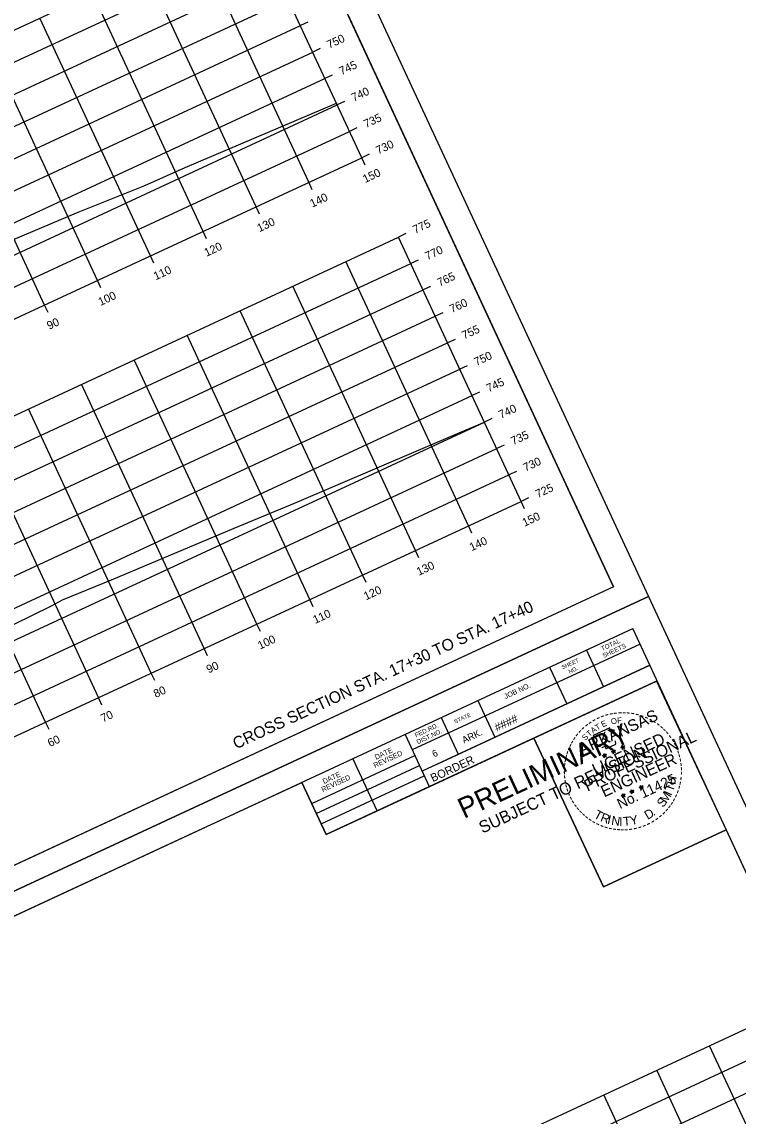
# Model space of a CAD drawing. Extents: x 1354696 to 1366163, y 660729 to 670380.
# Drawn here: x 1358197.6 to 1358320.5, y 665980.8 to 666168.5 of the extents above; entities that cross this region are included whole.
import ezdxf

# ---------------------------------------------------------------- set-up
doc = ezdxf.new("R2010")
doc.units = 0
for name, color, linetype in [('R_Axis', 7, 'Continuous'), ('R_Axis Annot', 7, 'Continuous'), ('R_Border', 7, 'Continuous'), ('R_Border PE', 7, 'Continuous'), ('R_Border Prem', 7, 'Continuous'), ('R_Draft', 7, 'Continuous'), ('R_Exist Surface', 7, 'Continuous'), ('R_Grid', 7, 'Continuous'), ('R_No Plot', 7, 'Continuous')]:
    doc.layers.add(name, color=color, linetype=linetype)

msp = doc.modelspace()

# ---------------------------------------------------------------- linework, layer by layer
at = {"layer": 'R_Axis'}
for p, q in [((1358255.9, 666145.21), (1358236.95, 666186.02)), ((1358246.64, 666168.47), (1358245.37, 666167.88)), ((1358248.75, 666163.94), (1358247.48, 666163.35)), ((1358250.85, 666159.4), (1358249.58, 666158.81)), ((1358252.96, 666154.87), (1358251.69, 666154.28)), ((1358255.06, 666150.33), (1358253.79, 666149.74)), ((1357983.8, 666018.88), (1358255.9, 666145.21)), ((1358257.17, 666145.8), (1358255.9, 666145.21)), ((1358256.49, 666143.94), (1358255.9, 666145.21)), ((1358247.42, 666139.73), (1358246.83, 666141)), ((1358238.35, 666135.52), (1358237.76, 666136.79)), ((1358229.28, 666131.31), (1358228.69, 666132.58)), ((1358263.49, 666132.19), (1358262.22, 666131.6)), ((1358283.27, 666086.25), (1358262.22, 666131.6)), ((1358220.21, 666127.1), (1358219.62, 666128.37)), ((1358265.59, 666127.66), (1358264.32, 666127.07)), ((1358211.14, 666122.88), (1358210.55, 666124.15)), ((1358267.7, 666123.12), (1358266.43, 666122.53)), ((1358202.07, 666118.67), (1358201.48, 666119.94)), ((1358269.8, 666118.59), (1358268.53, 666118)), ((1358271.91, 666114.05), (1358270.64, 666113.46)), ((1358274.01, 666109.52), (1358272.74, 666108.93)), ((1358276.12, 666104.98), (1358274.85, 666104.39)), ((1358278.22, 666100.45), (1358276.95, 666099.86)), ((1358280.33, 666095.91), (1358279.06, 666095.32)), ((1358282.44, 666091.38), (1358281.17, 666090.79)), ((1358011.17, 665959.92), (1358283.27, 666086.25)), ((1358284.54, 666086.84), (1358283.27, 666086.25)), ((1358283.86, 666084.98), (1358283.27, 666086.25)), ((1358274.79, 666080.77), (1358274.2, 666082.04)), ((1358265.72, 666076.56), (1358265.13, 666077.83)), ((1358256.65, 666072.35), (1358256.06, 666073.62)), ((1358247.58, 666068.14), (1358246.99, 666069.41)), ((1358238.51, 666063.93), (1358237.92, 666065.2)), ((1358229.44, 666059.72), (1358228.85, 666060.99)), ((1358220.37, 666055.51), (1358219.78, 666056.78)), ((1358211.3, 666051.3), (1358210.71, 666052.57)), ((1358202.23, 666047.08), (1358201.64, 666048.35))]:
    msp.add_line(p, q, dxfattribs=at)
at = {"layer": 'R_Border'}
for p, q in [((1358299.11, 666071.56), (1358212.59, 666257.91)), ((1358299.11, 666071.56), (1358012.33, 665938.41)), ((1358015.65, 665931.27), (1358302.43, 666064.41)), ((1358388.95, 665878.06), (1358302.43, 666064.41)), ((1358303.67, 666061.75), (1358264.58, 666043.6)), ((1358303.66, 666061.76), (1358303.66, 666061.76)), ((1358294.45, 666060.71), (1358297.37, 666054.41)), ((1358305.35, 666058.12), (1358266.26, 666039.97)), ((1358268.94, 666041.21), (1358305.35, 666058.12)), ((1358288.15, 666057.78), (1358291.08, 666051.49)), ((1358306.59, 666055.45), (1358249.77, 666029.07)), ((1358275.84, 666052.07), (1358278.76, 666045.77)), ((1358269.54, 666049.14), (1358272.46, 666042.85)), ((1358263.34, 666046.26), (1358267.5, 666037.3)), ((1358247.31, 666034.39), (1358265.03, 666042.62)), ((1358258.55, 666033.15), (1358254.39, 666042.11)), ((1358248.09, 666032.7), (1358265.81, 666040.93)), ((1358248.91, 666030.94), (1358266.63, 666039.17)), ((1358249.77, 666029.07), (1358245.61, 666038.03))]:
    msp.add_line(p, q, dxfattribs=at)
at = {"layer": 'R_Border PE'}
for p, q in [((1358297.59, 666042.61), (1358297.44, 666042.94)), ((1358297.44, 666042.94), (1358297.59, 666042.74)), ((1358297.44, 666042.94), (1358297.51, 666042.7)), ((1358297.86, 666042.86), (1358297.59, 666042.61)), ((1358297.86, 666042.86), (1358297.62, 666042.69)), ((1358297.86, 666042.86), (1358297.72, 666042.68)), ((1358298.74, 666043.27), (1358298.99, 666043.34)), ((1358298.74, 666043.27), (1358299.11, 666043.32)), ((1358298.74, 666043.27), (1358299.01, 666043.26)), ((1358299.11, 666043.32), (1358298.95, 666043.65)), ((1358298.95, 666043.65), (1358299.1, 666043.44)), ((1358298.95, 666043.65), (1358299.02, 666043.4)), ((1358299.04, 666042.96), (1358299.11, 666043.32)), ((1358299.04, 666042.96), (1358299.14, 666043.24)), ((1358299.04, 666042.96), (1358299.05, 666043.23)), ((1358299.38, 666043.56), (1358299.11, 666043.32)), ((1358299.43, 666043.14), (1358299.11, 666043.32)), ((1358299.38, 666043.56), (1358299.14, 666043.4)), ((1358299.43, 666043.14), (1358299.14, 666043.24)), ((1358299.43, 666043.14), (1358299.18, 666043.34)), ((1358299.38, 666043.56), (1358299.23, 666043.38)), ((1358300.35, 666044), (1358300.6, 666044.07)), ((1358300.35, 666044), (1358300.71, 666044.05)), ((1358300.35, 666044), (1358300.62, 666043.99)), ((1358300.71, 666044.05), (1358300.56, 666044.38)), ((1358300.56, 666044.38), (1358300.71, 666044.17)), ((1358300.56, 666044.38), (1358300.63, 666044.13)), ((1358300.64, 666043.69), (1358300.71, 666044.05)), ((1358300.64, 666043.69), (1358300.75, 666043.97)), ((1358300.64, 666043.69), (1358300.65, 666043.96)), ((1358300.98, 666044.29), (1358300.71, 666044.05)), ((1358301.03, 666043.87), (1358300.71, 666044.05)), ((1358300.98, 666044.29), (1358300.74, 666044.13)), ((1358301.03, 666043.87), (1358300.75, 666043.97)), ((1358301.03, 666043.87), (1358300.78, 666044.07)), ((1358300.98, 666044.29), (1358300.84, 666044.12)), ((1358297.23, 666042.57), (1358297.48, 666042.63)), ((1358297.23, 666042.57), (1358297.59, 666042.61)), ((1358297.23, 666042.57), (1358297.5, 666042.56)), ((1358297.52, 666042.25), (1358297.59, 666042.61)), ((1358297.52, 666042.25), (1358297.63, 666042.54)), ((1358297.52, 666042.25), (1358297.53, 666042.53)), ((1358297.91, 666042.43), (1358297.59, 666042.61)), ((1358297.91, 666042.43), (1358297.63, 666042.54)), ((1358297.91, 666042.43), (1358297.66, 666042.64)), ((1358303.9, 666037.18), (1358303.75, 666037.51)), ((1358303.75, 666037.51), (1358303.9, 666037.31)), ((1358303.75, 666037.51), (1358303.81, 666037.27)), ((1358304.17, 666037.43), (1358303.9, 666037.18)), ((1358304.17, 666037.43), (1358303.93, 666037.26)), ((1358304.22, 666037), (1358303.97, 666037.21)), ((1358304.17, 666037.43), (1358304.03, 666037.25)), ((1358300.42, 666035.7), (1358300.66, 666035.76)), ((1358300.42, 666035.7), (1358300.78, 666035.74)), ((1358300.42, 666035.7), (1358300.68, 666035.69)), ((1358300.78, 666035.74), (1358300.63, 666036.07)), ((1358300.63, 666036.07), (1358300.77, 666035.87)), ((1358300.63, 666036.07), (1358300.69, 666035.83)), ((1358300.71, 666035.38), (1358300.78, 666035.74)), ((1358300.71, 666035.38), (1358300.81, 666035.67)), ((1358300.71, 666035.38), (1358300.72, 666035.66)), ((1358301.05, 666035.99), (1358300.78, 666035.74)), ((1358301.1, 666035.56), (1358300.78, 666035.74)), ((1358301.05, 666035.99), (1358300.81, 666035.82)), ((1358301.1, 666035.56), (1358300.81, 666035.67)), ((1358301.1, 666035.56), (1358300.85, 666035.77)), ((1358301.05, 666035.99), (1358300.9, 666035.81)), ((1358301.93, 666036.4), (1358302.18, 666036.46)), ((1358301.93, 666036.4), (1358302.29, 666036.45)), ((1358301.93, 666036.4), (1358302.2, 666036.39)), ((1358302.29, 666036.45), (1358302.14, 666036.78)), ((1358302.14, 666036.78), (1358302.29, 666036.57)), ((1358302.14, 666036.78), (1358302.21, 666036.53)), ((1358302.22, 666036.08), (1358302.29, 666036.45)), ((1358302.22, 666036.08), (1358302.32, 666036.37)), ((1358302.22, 666036.08), (1358302.23, 666036.36)), ((1358302.56, 666036.69), (1358302.29, 666036.45)), ((1358302.61, 666036.27), (1358302.29, 666036.45)), ((1358302.56, 666036.69), (1358302.32, 666036.53)), ((1358302.61, 666036.27), (1358302.33, 666036.37)), ((1358302.61, 666036.27), (1358302.36, 666036.47)), ((1358302.56, 666036.69), (1358302.42, 666036.51)), ((1358303.54, 666037.13), (1358303.78, 666037.2)), ((1358303.54, 666037.13), (1358303.9, 666037.18)), ((1358303.54, 666037.13), (1358303.8, 666037.12)), ((1358303.83, 666036.82), (1358303.9, 666037.18)), ((1358303.83, 666036.82), (1358303.93, 666037.11)), ((1358303.83, 666036.82), (1358303.84, 666037.09)), ((1358304.22, 666037), (1358303.9, 666037.18)), ((1358304.22, 666037), (1358303.93, 666037.1))]:
    msp.add_line(p, q, dxfattribs=at)
for points in [[(1358299.21, 666046.74), (1358299.22, 666047.06), (1358298.61, 666046.75), (1358298.46, 666047.41), (1358295.63, 666046.1)], [(1358295.63, 666046.1), (1358296.23, 666045.46)], [(1358297.1, 666044.11), (1358297.14, 666044.03), (1358297.66, 666044.25), (1358297.81, 666043.8), (1358299.5, 666044.59), (1358299.46, 666045.16)], [(1358297.44, 666042.94), (1358297.91, 666042.43), (1358297.23, 666042.57), (1358297.86, 666042.86), (1358297.52, 666042.25), (1358297.44, 666042.94)], [(1358298.95, 666043.65), (1358299.43, 666043.14), (1358298.74, 666043.27), (1358299.38, 666043.56), (1358299.04, 666042.96), (1358298.95, 666043.65)], [(1358300.56, 666044.38), (1358301.03, 666043.87), (1358300.35, 666044), (1358300.98, 666044.29), (1358300.64, 666043.69), (1358300.56, 666044.38)], [(1358303.75, 666037.51), (1358304.22, 666037), (1358303.54, 666037.13), (1358304.17, 666037.43), (1358303.83, 666036.82), (1358303.75, 666037.51)], [(1358300.63, 666036.07), (1358301.1, 666035.56), (1358300.42, 666035.7), (1358301.05, 666035.99), (1358300.71, 666035.38), (1358300.63, 666036.07)], [(1358302.14, 666036.78), (1358302.61, 666036.27), (1358301.93, 666036.4), (1358302.56, 666036.69), (1358302.22, 666036.08), (1358302.14, 666036.78)]]:
    msp.add_lwpolyline(points, dxfattribs=at)
for centre, radius in [((1358299.11, 666043.32), 0.172), ((1358299.11, 666043.32), 0.145), ((1358299.11, 666043.32), 0.116), ((1358299.11, 666043.32), 0.0991), ((1358299.11, 666043.32), 0.0747), ((1358299.11, 666043.32), 0.0495), ((1358299.11, 666043.32), 0.0296), ((1358300.71, 666044.05), 0.172), ((1358300.71, 666044.05), 0.145), ((1358300.71, 666044.05), 0.116), ((1358300.71, 666044.05), 0.0991), ((1358300.71, 666044.05), 0.0747), ((1358300.71, 666044.05), 0.0495), ((1358300.71, 666044.05), 0.0296), ((1358297.59, 666042.61), 0.172), ((1358297.59, 666042.61), 0.145), ((1358297.59, 666042.61), 0.116), ((1358297.59, 666042.61), 0.0991), ((1358297.59, 666042.61), 0.0747), ((1358297.59, 666042.61), 0.0495), ((1358297.59, 666042.61), 0.0296), ((1358303.9, 666037.18), 0.172), ((1358303.9, 666037.18), 0.145), ((1358303.9, 666037.18), 0.116), ((1358303.9, 666037.18), 0.0991), ((1358303.9, 666037.18), 0.0747), ((1358303.9, 666037.18), 0.0495), ((1358303.9, 666037.18), 0.0296), ((1358300.78, 666035.74), 0.172), ((1358300.78, 666035.74), 0.145), ((1358300.78, 666035.74), 0.116), ((1358300.78, 666035.74), 0.0991), ((1358300.78, 666035.74), 0.0747), ((1358300.78, 666035.74), 0.0495), ((1358300.78, 666035.74), 0.0296), ((1358302.29, 666036.44), 0.172), ((1358302.29, 666036.44), 0.145), ((1358302.29, 666036.44), 0.116), ((1358302.29, 666036.44), 0.0991), ((1358302.29, 666036.44), 0.0747), ((1358302.29, 666036.44), 0.0495), ((1358302.29, 666036.44), 0.0296)]:
    msp.add_circle(centre, radius, dxfattribs=at)
at = {"layer": 'R_Exist Surface'}
for points in [[(1358186.45, 666127.1), (1358206.94, 666135.75), (1358218.7, 666140.43), (1358225.57, 666143.53), (1358251.55, 666154.57)], [(1358189.54, 666061.93), (1358202.65, 666068.33), (1358204.55, 666069.34), (1358212.98, 666072.79), (1358233.98, 666081.67), (1358244.34, 666085.95), (1358272.72, 666098.06), (1358276.97, 666099.82)]]:
    msp.add_lwpolyline(points, dxfattribs=at)
at = {"layer": 'R_Grid'}
for p, q in [((1357964.85, 666059.69), (1358236.95, 666186.02)), ((1358255.9, 666145.21), (1358236.95, 666186.02)), ((1358246.83, 666141), (1358227.88, 666181.81)), ((1357966.95, 666055.16), (1358239.06, 666181.49)), ((1357969.06, 666050.62), (1358241.16, 666176.95)), ((1358237.76, 666136.79), (1358218.81, 666177.6)), ((1357971.16, 666046.09), (1358243.27, 666172.42)), ((1358228.69, 666132.58), (1358209.74, 666173.39)), ((1358219.62, 666128.37), (1358200.67, 666169.18)), ((1357973.27, 666041.55), (1358245.37, 666167.88)), ((1358210.55, 666124.15), (1358191.6, 666164.97)), ((1357975.37, 666037.02), (1358247.48, 666163.35)), ((1358201.48, 666119.94), (1358182.53, 666160.76)), ((1357977.48, 666032.48), (1358249.58, 666158.81)), ((1357979.58, 666027.95), (1358251.69, 666154.28)), ((1357981.69, 666023.41), (1358253.79, 666149.74)), ((1357983.8, 666018.88), (1358255.9, 666145.21)), ((1357990.11, 666005.27), (1358262.22, 666131.6)), ((1358283.27, 666086.25), (1358262.22, 666131.6)), ((1358274.2, 666082.04), (1358253.15, 666127.39)), ((1357992.22, 666000.74), (1358264.32, 666127.07)), ((1357994.32, 665996.2), (1358266.43, 666122.53)), ((1358265.13, 666077.83), (1358244.08, 666123.18)), ((1357996.43, 665991.67), (1358268.53, 666118)), ((1358256.06, 666073.62), (1358235.01, 666118.97)), ((1358246.99, 666069.41), (1358225.94, 666114.76)), ((1357998.53, 665987.13), (1358270.64, 666113.46)), ((1358237.92, 666065.2), (1358216.86, 666110.55)), ((1358000.64, 665982.6), (1358272.74, 666108.93)), ((1358228.85, 666060.99), (1358207.79, 666106.34)), ((1358002.74, 665978.06), (1358274.85, 666104.39)), ((1358219.78, 666056.78), (1358198.72, 666102.13)), ((1358004.85, 665973.53), (1358276.95, 666099.86)), ((1358210.71, 666052.57), (1358189.65, 666097.92)), ((1358006.96, 665968.99), (1358279.06, 666095.32)), ((1358201.64, 666048.35), (1358180.58, 666093.7)), ((1358009.06, 665964.46), (1358281.17, 666090.79)), ((1358011.17, 665959.92), (1358283.27, 666086.25)), ((1358052.58, 665870.73), (1358324.68, 665997.06)), ((1358054.68, 665866.19), (1358326.79, 665992.52)), ((1358336.67, 665947.5), (1358315.61, 665992.85)), ((1358327.6, 665943.29), (1358306.54, 665988.64)), ((1358056.79, 665861.66), (1358328.89, 665987.99)), ((1358318.53, 665939.08), (1358297.47, 665984.43))]:
    msp.add_line(p, q, dxfattribs=at)
at = {"layer": 'R_No Plot'}
for p, q in [((1358002.76, 665929.58), (1358305.1, 666069.95)), ((1358002.76, 665929.58), (1358305.1, 666069.95)), ((1358294.31, 666024.99), (1358294.31, 666024.99))]:
    msp.add_line(p, q, dxfattribs=at)
for points in [[(1357912.92, 666123.08), (1358215.26, 666263.45), (1358305.1, 666069.95), (1358002.76, 665929.58)], [(1358137.98, 666223.27), (1358155.78, 666231.53), (1358159.94, 666222.57), (1358174.55, 666229.36), (1358195.59, 666239.13), (1358207.56, 666213.64), (1358228.61, 666223.41), (1358299.11, 666071.56), (1358012.33, 665938.41), (1357925.81, 666124.77)], [(1358002.76, 665929.58), (1358305.1, 666069.95), (1358394.94, 665876.45), (1358092.59, 665736.08)], [(1358285.43, 666045.63), (1358306.48, 666055.4), (1358318.45, 666029.91), (1358297.4, 666020.14)], [(1358227.82, 666029.77), (1358245.61, 666038.03), (1358249.77, 666029.07), (1358264.39, 666035.86), (1358285.43, 666045.63), (1358297.4, 666020.14), (1358318.45, 666029.91), (1358388.95, 665878.06), (1358102.17, 665744.91), (1358015.65, 665931.27)]]:
    msp.add_lwpolyline(points, close=True, dxfattribs=at)

# ---------------------------------------------------------------- texts
at = {"layer": 'R_Axis Annot'}
for s, p in [('750', (1358250.31, 666163.89)), ('745', (1358252.42, 666159.36)), ('740', (1358254.52, 666154.82)), ('735', (1358256.63, 666150.29)), ('730', (1358258.73, 666145.75)), ('150', (1358256.47, 666140.85)), ('140', (1358247.4, 666136.63)), ('130', (1358238.33, 666132.42)), ('775', (1358265.05, 666132.15)), ('120', (1358229.26, 666128.21)), ('770', (1358267.16, 666127.61)), ('110', (1358220.55, 666124.17)), ('765', (1358269.26, 666123.08)), ('100', (1358211.07, 666119.77)), ('760', (1358271.37, 666118.54)), ('90', (1358202.26, 666115.68)), ('755', (1358273.47, 666114.01)), ('750', (1358275.58, 666109.47)), ('745', (1358277.68, 666104.94)), ('740', (1358279.79, 666100.4)), ('735', (1358281.89, 666095.87)), ('730', (1358284, 666091.33)), ('725', (1358286.11, 666086.8)), ('150', (1358283.84, 666081.89)), ('140', (1358274.77, 666077.68)), ('130', (1358265.7, 666073.47)), ('120', (1358256.63, 666069.26)), ('110', (1358247.92, 666065.21)), ('100', (1358238.44, 666060.81)), ('90', (1358229.63, 666056.72)), ('80', (1358220.56, 666052.51)), ('70', (1358211.49, 666048.3)), ('60', (1358202.39, 666044.07))]:
    msp.add_text(s, height=1.4, rotation=24.9042, dxfattribs=at).set_placement(p)
at = {"layer": 'R_Border'}
for s, height, p in [('TOTAL', 0.782, (1358297.2, 666060.57)), ('SHEETS', 0.782, (1358297.44, 666059.38)), ('SHEET', 0.684, (1358290.38, 666057.41)), ('NO.', 0.684, (1358291.58, 666056.66)), ('JOB NO.', 0.879, (1358280.57, 666052.32)), ('STATE', 0.684, (1358271.96, 666048.11)), ('####', 1.4, (1358279.08, 666046.73)), ('FED.RD.', 0.782, (1358265.22, 666045.73)), ('DIST.NO.', 0.782, (1358265.53, 666044.57)), ('ARK.', 1.172, (1358273.44, 666044.69)), ('REVISED', 0.879, (1358258.16, 666040.5)), ('DATE', 0.879, (1358258.37, 666041.9)), ('6', 1.17, (1358268.31, 666042.31)), ('BORDER', 1.4, (1358268.1, 666038.06)), ('REVISED', 0.879, (1358249.22, 666036.35)), ('DATE', 0.879, (1358249.43, 666037.75))]:
    msp.add_text(s, height=height, rotation=24.9042, dxfattribs=at).set_placement(p)
at = {"layer": 'R_Border PE'}
for s, height, rotation, p in [('ARKANSAS', 2, 24.9042, (1358293.74, 666042.7)), ('-', 1.6, 35.1235, (1358295.15, 666047.56)), ('-', 1.6, 30.801, (1358295.76, 666047.97)), ('-', 1.6, 25.0904, (1358296.43, 666048.36)), ('-', 1.6, 22.6472, (1358297.1, 666048.65)), ('E', 1, 25.7365, (1358297.27, 666047.45)), ('-', 1.6, 17.0659, (1358297.79, 666048.92)), ('-', 1.6, 12.1091, (1358298.49, 666049.11)), ('O', 1, 15.3557, (1358298.81, 666047.94)), ('-', 1.6, 7.2404, (1358299.14, 666049.24)), ('F', 1, 4.9748, (1358299.77, 666048.13)), ('-', 1.6, 2.7593, (1358299.9, 666049.35)), ('-', 1.6, 359.0253, (1358300.58, 666049.37)), ('-', 1.6, 354.5451, (1358301.23, 666049.36)), ('-', 1.6, 350.7668, (1358301.96, 666049.3)), ('-', 1.6, 345.4339, (1358302.69, 666049.17)), ('-', 1.6, 340.4828, (1358303.44, 666048.98)), ('-', 1.6, 334.7839, (1358304.19, 666048.72)), ('-', 1.6, 331.5563, (1358304.92, 666048.4)), ('-', 1.4, 328.5795, (1358305.6, 666048.08)), ('-', 1.6, 49.2114, (1358293.56, 666046.09)), ('-', 1.6, 44.0802, (1358294.02, 666046.6)), ('-', 1.6, 38.5343, (1358294.6, 666047.13)), ('T', 1, 41.3078, (1358294.97, 666045.8)), ('A', 1, 36.1173, (1358295.61, 666046.38)), ('T', 1, 30.9269, (1358296.31, 666046.89)), ('-', 1.6, 324.5725, (1358306.15, 666047.67)), ('-', 1.6, 319.567, (1358306.7, 666047.25)), ('-', 1.6, 315.477, (1358307.17, 666046.83)), ('-', 1.6, 310.0274, (1358307.63, 666046.41)), ('-', 1.6, 61.1359, (1358292.38, 666044.34)), ('-', 1.6, 58.9677, (1358292.74, 666044.94)), ('-', 1.6, 53.696, (1358293.12, 666045.53)), ('S', 1, 46.4982, (1358294.28, 666045.12)), ('PROFESSIONAL', 2, 24.9042, (1358294.64, 666036.44)), ('LICENSED', 2, 24.9042, (1358296.03, 666039.19)), ('-', 1.6, 305.4535, (1358308.12, 666045.82)), ('-', 1.6, 301.5003, (1358308.59, 666045.19)), ('-', 1.6, 299.2343, (1358308.95, 666044.56)), ('-', 1.6, 73.3272, (1358291.68, 666042.62)), ('-', 1.6, 67.8664, (1358291.89, 666043.24)), ('-', 1.6, 63.8548, (1358292.11, 666043.8)), ('ENGINEER', 2, 24.9042, (1358297.51, 666035.44)), ('DWB', 0.01, 24.9042, (1358299.1, 666043.31)), ('DWB', 0.01, 24.9042, (1358300.7, 666044.04)), ('-', 1.6, 294.8448, (1358309.25, 666044)), ('-', 1.6, 288.4214, (1358309.51, 666043.39)), ('-', 1.6, 285.8995, (1358309.72, 666042.77)), ('-', 1.6, 82.9748, (1358291.31, 666040.7)), ('-', 1.6, 79.1366, (1358291.39, 666041.32)), ('-', 1.6, 75.5183, (1358291.52, 666042.01)), ('DWB', 0.01, 24.9042, (1358297.58, 666042.6)), ('-', 1.6, 280.6668, (1358309.91, 666042.11)), ('-', 1.6, 277.7723, (1358310.05, 666041.38)), ('-', 1.6, 92.6784, (1358291.31, 666039.35)), ('-', 1.6, 87.7755, (1358291.29, 666040.01)), ('-', 1.6, 97.2986, (1358291.38, 666038.69)), ('No. 11425', 1.757, 24.9042, (1358300.23, 666033.44)), ('H', 1.54, 79.513, (1358309.73, 666037.55)), ('-', 1.6, 272.7928, (1358310.13, 666040.67)), ('-', 1.6, 269.5239, (1358310.16, 666039.99)), ('-', 1.6, 100.3651, (1358291.5, 666037.96)), ('-', 1.6, 106.1054, (1358291.68, 666037.25)), ('T', 1.54, 71.5486, (1358309.32, 666036.32)), ('-', 1.6, 256.1579, (1358309.87, 666037.69)), ('-', 1.6, 258.7494, (1358310.03, 666038.38)), ('-', 1.6, 263.9754, (1358310.12, 666039.14)), ('-', 1.6, 110.0905, (1358291.9, 666036.6)), ('-', 1.6, 113.9664, (1358292.17, 666035.95)), ('-', 1.6, 119.1, (1358292.51, 666035.31)), ('DWB', 0.01, 24.9042, (1358300.77, 666035.73)), ('DWB', 0.01, 24.9042, (1358302.28, 666036.44)), ('DWB', 0.01, 24.9042, (1358303.89, 666037.17)), ('S', 1.54, 51.8354, (1358307.61, 666033.62)), ('M', 1.54, 57.5605, (1358308.2, 666034.34)), ('I', 1.54, 67.0178, (1358309.01, 666035.65)), ('-', 1.6, 245.9893, (1358309.42, 666036.29)), ('-', 1.6, 250.6695, (1358309.68, 666036.97)), ('-', 1.6, 123.8521, (1358292.86, 666034.73)), ('-', 1.6, 126.6191, (1358293.29, 666034.12)), ('-', 1.6, 130.362, (1358293.69, 666033.65)), ('-', 1.6, 229.1558, (1358308.01, 666033.96)), ('-', 1.6, 232.261, (1358308.44, 666034.51)), ('-', 1.6, 237.1533, (1358308.8, 666035.06)), ('-', 1.6, 240.6405, (1358309.12, 666035.63)), ('-', 1.6, 133.9916, (1358294.15, 666033.17)), ('-', 1.6, 138.9685, (1358294.63, 666032.74)), ('-', 1.6, 140.633, (1358295.17, 666032.3)), ('-', 1.6, 145.3513, (1358295.74, 666031.92)), ('T', 1.54, 330.9447, (1358295.61, 666032.06)), ('R', 1.54, 338.9091, (1358296.74, 666031.43)), ('I', 1.54, 346.8735, (1358297.95, 666030.97)), ('N', 1.54, 351.4044, (1358298.66, 666030.78)), ('I', 1.54, 0.2645, (1358300.09, 666030.57)), ('T', 1.54, 4.7953, (1358300.83, 666030.55)), ('Y', 1.54, 12.7597, (1358302.12, 666030.66)), ('D', 1.54, 31.3011, (1358304.98, 666031.59)), ('.', 1.54, 38.6683, (1358306, 666032.21)), ('-', 1.6, 216.1899, (1358306.47, 666032.46)), ('-', 1.6, 220.3785, (1358307.05, 666032.94)), ('-', 1.6, 225.6226, (1358307.56, 666033.45)), ('-', 1.6, 150.7976, (1358296.34, 666031.58)), ('-', 1.6, 155.6223, (1358296.99, 666031.28)), ('-', 1.6, 159.128, (1358297.69, 666031)), ('-', 1.6, 163.838, (1358298.36, 666030.8)), ('-', 1.6, 169.5505, (1358299.03, 666030.67)), ('-', 1.6, 172.9939, (1358299.7, 666030.57)), ('-', 1.6, 176.4746, (1358300.36, 666030.52)), ('-', 1.6, 179.5044, (1358300.94, 666030.51)), ('-', 1.6, 183.4654, (1358301.61, 666030.54)), ('-', 1.6, 187.7024, (1358302.32, 666030.64)), ('-', 1.6, 192.4597, (1358303.04, 666030.79)), ('-', 1.6, 198.0196, (1358303.79, 666031.02)), ('-', 1.6, 201.4224, (1358304.49, 666031.29)), ('-', 1.6, 206.4959, (1358305.16, 666031.62)), ('-', 1.6, 210.7208, (1358305.86, 666032.03))]:
    msp.add_text(s, height=height, rotation=rotation, dxfattribs=at).set_placement(p)
at = {"layer": 'R_Border Prem'}
for s, height, p in [('PRELIMINARY', 3.5, (1358273.44, 666031.75)), ('SUBJECT TO REVISION', 2.0751, (1358276.61, 666029.22)), ('DWB', 0.01, (1358273.34, 666033.74))]:
    msp.add_text(s, height=height, rotation=24.9042, dxfattribs=at).set_placement(p)
at = {"layer": 'R_Draft'}
msp.add_text('CROSS SECTION STA. 17+30 TO STA. 17+40', height=2, rotation=24.9042, dxfattribs=at).set_placement((1358234.34, 666043.69))

doc.saveas('drawing.dxf')
